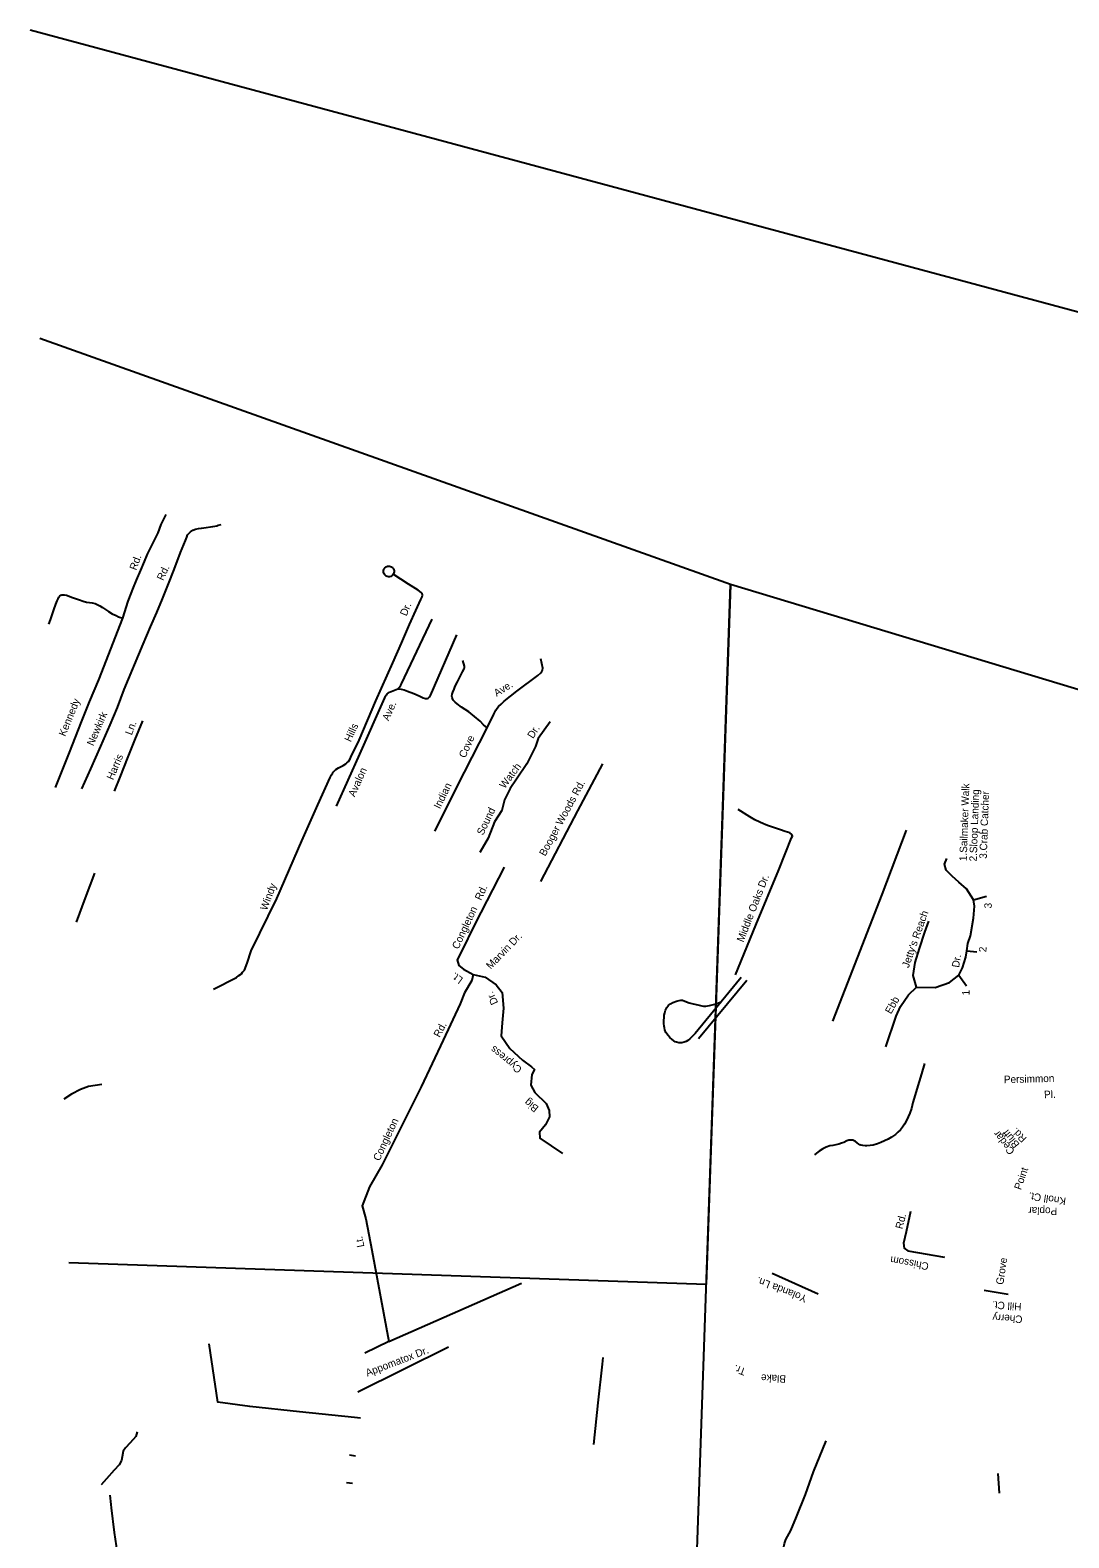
# Model space of a CAD drawing. Extents: x 2308163 to 2335412, y -96774 to 125428.
# Drawn here: x 2321175 to 2321460.1, y 52737.2 to 53151 of the extents above; entities that cross this region are included whole.
import ezdxf

# ---------------------------------------------------------------- set-up
doc = ezdxf.new("R2010")
doc.units = 0
for name, color, linetype in [('Old_Level_10', 7, 'Continuous'), ('Old_Level_35', 7, 'Continuous'), ('Old_Level_63', 7, 'Continuous')]:
    doc.layers.add(name, color=color, linetype=linetype)

msp = doc.modelspace()

# ---------------------------------------------------------------- linework, layer by layer
at = {"layer": 'Old_Level_35'}
for p, q in [((2321358.43, 52874.23), (2321371.7, 52890.23)), ((2321370.16, 52891.01), (2321364.68, 52884.33)), ((2321265.67, 52770.06), (2321263.99, 52770.22)), ((2321264.29, 52759.59), (2321262.67, 52759.87)), ((2321195.92, 52753.36), (2321194.47, 52751.74)), ((2321263.49, 52752.1), (2321261.87, 52752.27)), ((2321440.65, 52754.87), (2321440.98, 52749.48)), ((2321196.81, 52748.92), (2321197.11, 52746.37))]:
    msp.add_line(p, q, dxfattribs=at)
for points in [[(2321200.42, 52989.61), (2321201.87, 52994.26), (2321203.34, 52997.97), (2321204.21, 53000.01), (2321205.37, 53002.8), (2321206.36, 53005.14), (2321207.24, 53007.18), (2321209.29, 53011.38), (2321210.09, 53012.99), (2321210.97, 53015.33), (2321212.3, 53018.05)], [(2321189.17, 52942.75), (2321191.64, 52948.27), (2321194.36, 52954.46), (2321196.95, 52960.35), (2321199, 52965.11), (2321200.78, 52969.99), (2321206.03, 52982.45), (2321208.05, 52987.21), (2321209.72, 52991.17), (2321211.27, 52994.94), (2321212.95, 52999.01), (2321214.5, 53002.98), (2321216.3, 53007.6), (2321217.16, 53009.79), (2321217.61, 53010.89), (2321217.96, 53011.82), (2321218.21, 53012.44), (2321218.6, 53012.93), (2321218.99, 53013.29), (2321219.62, 53013.71), (2321220.39, 53014), (2321221.21, 53014.18), (2321222.04, 53014.29), (2321223.27, 53014.44), (2321224.52, 53014.64), (2321225.14, 53014.77), (2321226.19, 53014.96), (2321226.63, 53015.08), (2321227.45, 53015.31)], [(2321274.68, 53001.67), (2321274.48, 53001.41), (2321274.26, 53001.23), (2321273.99, 53001.07), (2321273.66, 53000.98), (2321273.32, 53000.98), (2321273.01, 53001.04), (2321272.76, 53001.16), (2321272.52, 53001.32), (2321272.33, 53001.51), (2321272.17, 53001.75), (2321272.07, 53001.95), (2321272.02, 53002.19), (2321271.99, 53002.44), (2321272.02, 53002.66), (2321272.07, 53002.91), (2321272.18, 53003.11), (2321272.31, 53003.33), (2321272.48, 53003.5), (2321272.66, 53003.65), (2321272.88, 53003.75), (2321273.08, 53003.82), (2321273.37, 53003.88), (2321273.64, 53003.86), (2321273.93, 53003.8), (2321274.15, 53003.7), (2321274.34, 53003.55), (2321274.49, 53003.44), (2321274.63, 53003.26), (2321274.74, 53003.1), (2321274.82, 53002.9), (2321274.87, 53002.69), (2321274.89, 53002.5), (2321274.89, 53002.27), (2321274.86, 53002.07), (2321274.8, 53001.87), (2321274.68, 53001.67)], [(2321253.98, 52938.34), (2321257.3, 52945.88), (2321257.69, 52946.63), (2321257.95, 52946.99), (2321258.2, 52947.36), (2321258.53, 52947.73), (2321258.92, 52948.09), (2321259.61, 52948.52), (2321260.88, 52949.18), (2321261.64, 52949.59), (2321261.95, 52949.85), (2321262.38, 52950.28), (2321262.8, 52950.94), (2321262.98, 52951.4), (2321265.28, 52956.07), (2321269.87, 52966.9), (2321274.56, 52977.32), (2321276.89, 52982.71), (2321279.13, 52987.85), (2321280.83, 52991.67), (2321282.2, 52994.75), (2321282.56, 52995.49), (2321282.65, 52995.89), (2321282.56, 52996.32), (2321282.33, 52996.61), (2321281.47, 52997.24), (2321278.88, 52998.89), (2321274.68, 53001.67)], [(2321180.11, 52987.94), (2321180.53, 52989.18), (2321181.47, 52991.91), (2321182.02, 52993.45), (2321182.38, 52994.37), (2321182.63, 52994.94), (2321182.88, 52995.37), (2321183.12, 52995.69), (2321183.37, 52995.87), (2321183.69, 52996), (2321183.9, 52996.02), (2321184.37, 52996), (2321185, 52995.88), (2321186.63, 52995.26), (2321188.49, 52994.59), (2321189.49, 52994.23), (2321190.47, 52993.96), (2321191.28, 52993.88), (2321192.01, 52993.79), (2321192.84, 52993.58), (2321193.39, 52993.38), (2321194.13, 52992.98), (2321194.88, 52992.5), (2321195.37, 52992.13), (2321196.47, 52991.41), (2321197.46, 52990.82), (2321198.57, 52990.29), (2321199.24, 52989.96), (2321200.42, 52989.61)], [(2321181.92, 52943.16), (2321185.75, 52952.74), (2321189.08, 52961.13), (2321191.24, 52966.63), (2321193.84, 52972.64), (2321200.42, 52989.61)], [(2321275.95, 52970.19), (2321276.35, 52970.64), (2321276.73, 52971.18), (2321276.93, 52971.61), (2321285.33, 52989.28)], [(2321275.95, 52970.19), (2321276.87, 52970.1), (2321277.63, 52969.9), (2321278.57, 52969.57), (2321280.3, 52968.9), (2321281.78, 52968.24), (2321282.9, 52967.71), (2321283.5, 52967.57), (2321283.96, 52967.56), (2321284.25, 52967.65), (2321284.44, 52967.78), (2321284.66, 52968.04), (2321284.86, 52968.41), (2321292.11, 52984.99)], [(2321300.4, 52959.47), (2321299.48, 52960.31), (2321298.5, 52961.28), (2321296.97, 52962.56), (2321295.37, 52963.85), (2321293.41, 52965.21), (2321292.18, 52966.05), (2321291.62, 52966.52), (2321291.32, 52966.89), (2321291.14, 52967.1), (2321290.9, 52967.52), (2321290.85, 52967.83), (2321290.79, 52968.22), (2321290.87, 52968.71), (2321291.06, 52969.27), (2321291.4, 52970.14), (2321291.68, 52970.89), (2321292.26, 52972.11), (2321292.99, 52973.6), (2321293.7, 52974.89), (2321294.1, 52975.7), (2321294.22, 52976.09), (2321294.24, 52976.44), (2321293.73, 52977.99)], [(2321300.4, 52959.47), (2321302.24, 52963.24), (2321302.83, 52964.35), (2321303.18, 52964.89), (2321303.6, 52965.36), (2321304.25, 52966.01), (2321305.08, 52966.8), (2321308.58, 52969.53), (2321314.31, 52973.9), (2321315.15, 52974.62), (2321315.42, 52974.96), (2321315.66, 52975.36), (2321315.75, 52975.87), (2321315.19, 52978.44)], [(2321259.04, 52937.97), (2321265.46, 52952.26), (2321272.33, 52967.73), (2321272.55, 52968.21), (2321272.69, 52968.41), (2321272.82, 52968.57), (2321273.01, 52968.78), (2321273.23, 52969.01), (2321273.36, 52969.11), (2321273.64, 52969.27), (2321275.95, 52970.19)], [(2321198.17, 52942.11), (2321199.66, 52945.93), (2321201.88, 52951.51), (2321203.73, 52956.08), (2321205.88, 52961.4)], [(2321286.08, 52931.12), (2321294.23, 52947.31), (2321300.4, 52959.47)], [(2321317.71, 52961.12), (2321314.41, 52956.53), (2321313.71, 52954.36), (2321311.35, 52949.58), (2321308.54, 52945.44), (2321306.72, 52942.83), (2321305.2, 52939.75), (2321304.47, 52936.79), (2321302.48, 52933.73), (2321300.76, 52929.24), (2321298.41, 52925.24)], [(2321315.19, 52917.35), (2321325.29, 52936.74), (2321332.24, 52949.58)], [(2321235.69, 52898.3), (2321242.68, 52912.66), (2321249.56, 52928.5), (2321253.98, 52938.34)], [(2321368.61, 52891.74), (2321374.18, 52905.3), (2321380.49, 52920.53), (2321384.03, 52929.26), (2321384.28, 52929.75), (2321384.1, 52930.19), (2321383.56, 52930.64), (2321382.93, 52930.84), (2321382.25, 52931.05), (2321381.01, 52931.52), (2321377.42, 52932.73), (2321376.73, 52932.93), (2321376.3, 52933.14), (2321375.31, 52933.59), (2321373.95, 52934.26), (2321372.59, 52935.03), (2321369.39, 52937.05)], [(2321395.31, 52878.96), (2321408.85, 52913.77), (2321415.53, 52931.37)], [(2321305.14, 52921.26), (2321297.19, 52905.79), (2321293.21, 52897.75), (2321292.22, 52895.78), (2321292.63, 52894.22), (2321293.98, 52893.25), (2321296.56, 52891.77), (2321299.93, 52891.04), (2321302.94, 52888.93), (2321304.57, 52886.86), (2321304.89, 52882.53), (2321304.59, 52878.53), (2321304.32, 52874.99), (2321306.67, 52871.51), (2321310.11, 52868.31), (2321312.61, 52866.41)], [(2321409.9, 52871.97), (2321412.69, 52880.4), (2321413.94, 52883.03), (2321416.14, 52886.2), (2321418.3, 52888.33), (2321423.41, 52888.27), (2321427.4, 52889.64), (2321429.91, 52891.64), (2321430.9, 52893.58), (2321431.82, 52896.56), (2321432.11, 52898.29), (2321432.41, 52900.26), (2321433.18, 52902.43), (2321433.93, 52907.28), (2321434.27, 52910.52), (2321433.99, 52912.27), (2321432, 52915.35), (2321429.97, 52917.16), (2321428.06, 52918.74), (2321426.49, 52920.42), (2321425.96, 52922.06), (2321426.6, 52923.66)], [(2321192.61, 52919.59), (2321190.11, 52912.87), (2321187.58, 52906.18)], [(2321433.99, 52912.27), (2321437.54, 52913.31)], [(2321418.3, 52888.33), (2321417.36, 52891.49), (2321417.95, 52895.07), (2321419.13, 52898.97), (2321420.56, 52903.45), (2321421.71, 52906.43)], [(2321225.33, 52887.81), (2321231.62, 52890.96), (2321232.3, 52891.48), (2321232.96, 52891.95), (2321233.31, 52892.42), (2321233.82, 52892.95), (2321234.54, 52894.94), (2321235.69, 52898.3)], [(2321432.11, 52898.29), (2321434.91, 52898.03)], [(2321296.56, 52891.77), (2321296.22, 52890.15), (2321294.26, 52886.77), (2321293.05, 52883.74), (2321288.4, 52873.81), (2321282.29, 52860.98), (2321271.58, 52839.57), (2321268.17, 52833.53), (2321266.14, 52828.31), (2321267.13, 52824.71), (2321268.8, 52816.16)], [(2321429.91, 52891.64), (2321432.07, 52888.65)], [(2321364.68, 52884.33), (2321357.59, 52875.63), (2321356.75, 52874.77), (2321356.11, 52874.17), (2321355.54, 52873.67), (2321355.12, 52873.39), (2321354.52, 52873.2), (2321353.89, 52873.07), (2321353.02, 52873.05), (2321352.46, 52873.18), (2321352.08, 52873.31), (2321351.22, 52873.93), (2321350.62, 52874.48), (2321350.12, 52875.04), (2321349.49, 52875.92), (2321349.23, 52876.64), (2321349.11, 52877.14), (2321349.07, 52877.58), (2321348.95, 52878.33), (2321348.93, 52879.13), (2321349, 52879.96), (2321349.08, 52880.59), (2321349.21, 52881.28), (2321349.43, 52881.97), (2321349.79, 52882.71), (2321350.02, 52883.12), (2321350.27, 52883.37), (2321350.78, 52883.73), (2321351.42, 52884.09), (2321352.43, 52884.45), (2321353.11, 52884.68), (2321353.62, 52884.78), (2321354.06, 52884.71), (2321354.73, 52884.51), (2321355.87, 52884.06), (2321356.99, 52883.7), (2321358.28, 52883.43), (2321359.35, 52883.2), (2321359.84, 52883.14), (2321360.52, 52883.12), (2321361.52, 52883.28), (2321362.98, 52883.69), (2321364.68, 52884.33)], [(2321420.55, 52867.36), (2321419.66, 52864.5), (2321419.04, 52862.45), (2321417.28, 52856.68), (2321416.93, 52855), (2321416.46, 52853.69), (2321416.06, 52852.71), (2321415.57, 52851.76), (2321415.01, 52850.73), (2321414.49, 52849.93), (2321413.91, 52849.19), (2321413.18, 52848.48), (2321412.51, 52847.85), (2321411.48, 52847.19), (2321410.51, 52846.63), (2321409.54, 52846.14), (2321408.54, 52845.68), (2321407.56, 52845.29), (2321406.42, 52844.97), (2321405.62, 52844.86), (2321404.68, 52844.79), (2321404.2, 52844.78), (2321403.61, 52844.82), (2321403.05, 52844.96), (2321402.78, 52845.08)], [(2321312.61, 52866.41), (2321313.42, 52865.72), (2321312.75, 52864.36), (2321312.42, 52861.4), (2321313.51, 52859.39), (2321316.65, 52856.35), (2321317.51, 52854.47), (2321317.6, 52852.77), (2321316.44, 52850.5), (2321314.83, 52848.55), (2321314.93, 52846.85), (2321321.11, 52842.62)], [(2321194.67, 52861.64), (2321191.03, 52861.01), (2321188.8, 52860.24), (2321186.33, 52858.99), (2321184.22, 52857.55)], [(2321402.78, 52845.08), (2321402.52, 52845.2), (2321402, 52845.55), (2321401.43, 52846.02), (2321401.16, 52846.17), (2321400.84, 52846.28), (2321400.34, 52846.34), (2321399.71, 52846.29), (2321399.14, 52846.1), (2321398.32, 52845.69), (2321397.69, 52845.46), (2321397.01, 52845.25), (2321396.12, 52845.05), (2321395.36, 52844.89), (2321394.54, 52844.73), (2321393.49, 52844.39), (2321392.59, 52843.96), (2321391.63, 52843.29), (2321390.87, 52842.75), (2321390.35, 52842.32)], [(2321416.64, 52826.77), (2321415.47, 52821.2), (2321414.75, 52818.05), (2321414.95, 52816.7), (2321415.9, 52815.93), (2321425.98, 52814.24)], [(2321268.8, 52816.16), (2321273.48, 52791.07), (2321266.84, 52787.86)], [(2321378.66, 52809.8), (2321391.36, 52804.17)], [(2321273.48, 52791.07), (2321309.86, 52807.04)], [(2321443.52, 52803.94), (2321436.88, 52805.03)], [(2321263.99, 52770.22), (2321248.96, 52771.78), (2321235.3, 52773.22), (2321226.5, 52774.38), (2321224.08, 52790.44)], [(2321264.97, 52777.27), (2321289.82, 52789.59)], [(2321332.23, 52786.71), (2321332.02, 52784.87), (2321330.8, 52774.24), (2321329.65, 52762.81)], [(2321204.36, 52766.27), (2321204, 52764.96), (2321202.44, 52763.26), (2321201.14, 52761.88), (2321200.52, 52760.95), (2321200.28, 52759.45), (2321200.04, 52758.44), (2321199.42, 52757.25), (2321198.05, 52755.75), (2321195.92, 52753.36)], [(2321381.82, 52734.39), (2321382.04, 52735.64), (2321382.46, 52736.76), (2321383.77, 52739.18), (2321385.41, 52742.99), (2321387.8, 52749.06), (2321390, 52755.31), (2321393.51, 52763.8)], [(2321197.11, 52746.37), (2321197.22, 52745.37), (2321198.07, 52738.63), (2321199.11, 52731.32), (2321199.7, 52726.46), (2321199.64, 52724.83), (2321199.03, 52723.26), (2321197.54, 52721.2), (2321195.98, 52719.62)]]:
    msp.add_lwpolyline(points, dxfattribs=at)
at = {"layer": 'Old_Level_63'}
for p, q in [((2321367.22, 52998.81), (2321177.64, 53066.34)), ((2321621.26, 52922.18), (2321367.22, 52998.81))]:
    msp.add_line(p, q, dxfattribs=at)
for points in [[(2322020.02, 52911.6), (2321937.45, 52945.83), (2321174.98, 53150.98)], [(2321367.21, 52998.76), (2321360.59, 52806.67), (2321185.64, 52812.7)], [(2321621.26, 52922.18), (2321607.1, 52511.43), (2321350.69, 52519.52), (2321367.22, 52998.81)]]:
    msp.add_lwpolyline(points, dxfattribs=at)

# ---------------------------------------------------------------- texts
at = {"layer": 'Old_Level_10'}
for s, height, rotation, p in [('Rd.', 2.051, 69.6167, (2321204.09, 53002.59)), ('Rd.', 2.051, 65.0847, (2321211.49, 52999.75)), ('Dr.', 2.051, 67.3169, (2321278.29, 52990.01)), ('Ave.', 2.051, 32.0499, (2321303.06, 52967.97)), ('Kennedy', 2.051, 67.8467, (2321184.61, 52956.99)), ('Newkirk', 2.051, 66.499, (2321192.32, 52954.38)), ('Ave.', 2.051, 66.0506, (2321273.37, 52961.24)), ('Ln.', 2.051, 69.1108, (2321202.87, 52957.34)), ('Hills', 2.051, 65.6411, (2321262.99, 52955.46)), ('Dr.', 2.051, 57.3171, (2321313.03, 52956.38)), ('Cove', 2.051, 65.514, (2321294.42, 52951.05)), ('Harris', 2.051, 67.3307, (2321197.77, 52945.03)), ('Avalon', 2.051, 65.8193, (2321264.05, 52940.37)), ('Watch', 2.051, 53.1139, (2321305.25, 52942.65)), ('Indian ', 2.051, 63.7995, (2321287.48, 52937.09)), ('Booger Woods Rd.', 2.0505, 61.6242, (2321316.4, 52924.1)), ('1.Sailmaker Walk', 2.0505, 88.0247, (2321432.1, 52922.87)), ('2.Sloop Landing', 2.0505, 88.0247, (2321434.85, 52922.79)), ('3.Crab Catcher', 2.0505, 88.0247, (2321437.6, 52923.52)), ('Sound ', 2.051, 64.3347, (2321299.33, 52929.85)), ('Windy', 2.051, 69.4786, (2321239.96, 52909.23)), ('Middle Oaks Dr.', 2.0505, 68.7633, (2321370.78, 52900.51)), ('Congleton   Rd.', 2.0505, 64.9615, (2321292.53, 52898.57)), ("Jetty's Reach", 2.0505, 70.5106, (2321416.16, 52893.46)), ('3', 2.05, 88.0247, (2321438.95, 52909.9)), ('Marvin Dr.', 2.051, 45.8234, (2321301.41, 52893.09)), ('Dr.', 2.051, 80.239, (2321429.98, 52893.57)), ('2', 2.05, 88.0247, (2321437.5, 52897.88)), ('Lt.', 2.051, 143.6523, (2321294.01, 52890.72)), ('Dr.', 2.051, 115.5158, (2321303.51, 52884.05)), ('Ebb ', 2.051, 60.3233, (2321411.31, 52880.78)), ('1', 2.05, 88.0247, (2321432.85, 52886.02)), ('Rd.', 2.051, 61.5377, (2321287.39, 52874.35)), ('Cypress', 2.051, 140.9663, (2321310.18, 52866.07)), ('Persimmon ', 2.051, 1.5076, (2321442.32, 52861.96)), ('Pl.', 2.051, 1.5076, (2321453.35, 52857.84)), ('Big', 2.051, 141.4721, (2321314.76, 52855.4)), ('Congleton', 2.051, 64.9413, (2321270.87, 52840.45)), ('Cedar ', 2.051, 128.3484, (2321445.42, 52843.33)), ('Bluff', 2.051, 128.3484, (2321446.73, 52845.17)), ('Rd.', 2.051, 134.7737, (2321448.71, 52846.92)), ('Point', 2.051, 71.0018, (2321446.98, 52832.53)), ('Knoll Ct.', 2.051, 171.486, (2321459.46, 52830.49)), ('Poplar', 2.051, 178.5533, (2321456.97, 52827.8)), ('Rd.', 2.051, 75.3776, (2321414.44, 52821.78)), ('Lt. ', 2.051, 101.4483, (2321266.76, 52817.12)), ('Chissom', 2.051, 169.6256, (2321421.81, 52812.61)), ('Grove ', 2.051, 81.4647, (2321442.12, 52806.54)), ('Yolanda Ln.', 2.0505, 158.6402, (2321388.45, 52803.55)), ('Hill Ct.', 2.051, 176.1975, (2321447.19, 52801.6)), ('Cherry ', 2.051, 176.1975, (2321447.47, 52798.13)), ('Appomatox Dr.', 2.0505, 20.8983, (2321267.53, 52781.42)), ('Tr.', 2.051, 159.6034, (2321371.69, 52783.57)), ('Blake', 2.051, 177.5682, (2321382.51, 52781.78))]:
    msp.add_text(s, height=height, rotation=rotation, dxfattribs=at).set_placement(p)

doc.saveas('drawing.dxf')
